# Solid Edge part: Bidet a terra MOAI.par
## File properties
Title: Bidet a terra MOAI
Author: DESYS
Template: Iso Part.par
Last saved by: PIM
Revision: 18
Application: Solid Edge
Tipo di contenuto documento: 0
Accuracy: 0,990
Document Number: 8607
Revision: 0
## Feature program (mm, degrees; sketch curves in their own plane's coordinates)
lofted protrusion "unnamed LoftedProtrusion 1"
lofted protrusion "unnamed LoftedProtrusion 2"
lofted protrusion "unnamed LoftedProtrusion 3"
lofted cutout "unnamed LoftedCutout 1"
thinwall "Spessoramento_2"  Thickness = 19 mm
thinwall "unnamed Thinwall 1"
thinwall "Spessoramento_4"  Thickness = 19 mm
sketch for "ProtrusioneEstrusa_1" plane through (-0.2644, 26.5251, -190) normal (0, 0, -1) x-axis (0, 1, 0)
  arc centre (3.4749, 0.2644) radius 35 from (-5.8954, -33.458) to (38.4749, 0.2644) ccw
  arc centre (3.4749, 0.2644) radius 35 from (38.4749, 0.2644) to (-22.0299, 24.2333) ccw
  arc centre (3.4749, 0.2644) radius 35 from (-22.0299, 24.2333) to (-31.5251, 0.2644) ccw
  arc centre (3.4749, 0.2644) radius 35 from (-31.5251, 0.2644) to (-21.0549, -24.7014) ccw
  arc centre (3.4749, 0.2644) radius 35 from (-21.0549, -24.7014) to (-5.8954, -33.458) ccw
extrude "ProtrusioneEstrusa_1" add through along -normal  Profile_Plane1_Distance = 15 mm
sketch for "unnamed Cutout 1" plane through (0.0007, 30, -150) normal (0, 0, 1) x-axis (-1, 0, 0)
  circle centre (0.0007, 0) radius 25
extrude "unnamed Cutout 1" cut through along -normal
sketch for "Foro_1" plane through (0, 54.9995, 0) normal (0, 0, 1) x-axis (-1, 0, 0)
  hole centre (0.0739, 199.9995) bore radius 17.5
hole "Foro_1" diameter 35 through
sketch for "ProtrusioneEstrusa_2"
  line (-125.0641, -18.0787) -> (-63.2077, -192.1962)
  line (-63.2077, -192.1962) -> (0.0001, -198.7066)
  line (0.0001, -159.2025) -> (0.0001, -198.7066)
  line (-44.6271, -121.0257) -> (0.0001, -159.2025)
  line (-90.7805, -18.0787) -> (-44.6271, -121.0257)
  line (-125.0641, -18.0787) -> (-90.7805, -18.0787)
extrude "ProtrusioneEstrusa_2" add finite 40 symmetric
fillet "Rotondo_1" radius 10
fillet "Rotondo_4" radius 5
sketch for "unnamed Cutout 2" plane through (0, -220, -205) normal (0, -1, 0) x-axis (1, 0, 0)
  line (88.2361, 175) -> (-88.2392, 175)
  arc centre (-88.2392, 150) radius 25 from (-88.2392, 175) to (-113.2363, 150.3801) ccw
  arc centre (1686.5556, 123.01) radius 1800 from (-113.2363, 150.3801) to (-92.0257, -153.8449) ccw
  arc centre (-67.3232, -149.9997) radius 25 from (-92.0257, -153.8449) to (-67.3232, -174.9997) ccw
  line (67.3229, -175) -> (-67.3232, -174.9997)
  arc centre (67.3229, -150) radius 25 from (67.3229, -175) to (92.0255, -153.8449) ccw
  arc centre (-1686.6002, 122.9957) radius 1800.0418 from (113.2332, 150.3803) to (92.0255, -153.8449) cw
  arc centre (88.2361, 150) radius 25 from (113.2332, 150.3803) to (88.2361, 175) ccw
  dimension (radial) = 0.0001
extrude "unnamed Cutout 2" cut through along -normal
fillet "Rotondo_9" radius 20
fillet "Rotondo_10" radius 5
fillet "Rotondo_12" radius 10
fillet "Rotondo_13" radius 5
sketch for "ProtrusioneEstrusa_3" plane through (0, 0, 0) normal (1, 0, 0) x-axis (0, 1, 0)
  line (-119.4631, -19) -> (-66.4893, -145.719)
  arc centre (-26.7858, -129.1213) radius 43.0331 from (-66.4893, -145.719) to (-37.7196, -170.7422) ccw
  line (-37.7196, -170.7422) -> (-5, -179.3377)
extrude "ProtrusioneEstrusa_3" add finite 40 symmetric
fillet "Rotondo_14" radius 5
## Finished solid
Body 1: solid body, 63 faces, 178 edges, 118 vertices.
  Faces by surface: cylinder 22, blend 12, plane 12, torus 10, offset 4, spline 3
  Edges by curve: intersection 65, circle 61, line 39, ellipse 8, curve on surface 4, spline 1
Bounding box of the edges (mm; curved faces can reach further): 383.076 x 550.236 x 410.000, from (-191.5381, -220, -410) to (191.5378, 330.2365, 0).
Cylindrical faces by radius (mm): R5 x11, R10 x1, R17.5 x1, R25 x5, R35 x1, R43.0331 x1, R1800 x1, R1800.0418 x1
Toroidal faces (ring radius, tube radius in mm): R22.5 r5 x1, R30 r5 x5, R38.0331 r5 x2, R1805 r5 x1, R1805.0418 r5 x1
Planar faces by outward normal: +x 1, +y 1, +z 2, -x 1, -y 1, -z 4, oblique 2
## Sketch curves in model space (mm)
arc centre (-523.5682, -220, -166.8251) radius 660 from (115, -220, 0) through (135.2082, -220, -206.9944) to (90, -220, -410)
arc centre (523.5682, -220, -166.8251) radius 660 from (-115, -220, 0) through (-135.2082, -220, -206.9944) to (-90, -220, -410)
arc centre (-47.8777, 30, 36.2494) radius 200 from (25, 30, -150) through (106.3667, 30, -91.0638) to (148.8098, 30, 0)
arc centre (48.0699, 30, 36.1741) radius 200 from (-25, 30, -150) through (-106.2646, 30, -91.0299) to (-148.6315, 30, 0)
arc centre (0, 119.5124, 13.9723) radius 200 from (0, 5, -150) through (0, -54.4926, -84.6293) to (0, -79.999, 0)
arc centre (0, 29.5721, 148.9204) radius 300 from (0, 290, 0) through (0, 190.9827, -103.9562) to (0, 55, -150)
circle centre (0, 30, -150) radius 25
arc centre (-49.1984, 40.6323, 0) radius 100 from (-119.9304, -30.0571, 0) through (-142.7572, 5.3229, 0) to (-148.9978, 46.9626, 0)
ellipse centre (0, 15.2559, 0) radii 274.7441, 150 from (149.0825, 45.5968, 0) through (-8.5444, 289.5539, 0) to (-148.9978, 46.9626, 0)
arc centre (49.266, 39.5415, 0) radius 100 from (118.4148, -32.6973, 0) through (142.3778, 3.0697, 0) to (149.0825, 45.5968, 0)
arc centre (0.5911, 90.3917, 0) radius 170.3917 from (118.4148, -32.6973, 0) through (-1.2963, -79.9895, 0) to (-119.9304, -30.0571, 0)
arc centre (619.961, 0, -156.6009) radius 824.961 from (-190, 0, 0) through (-203.4851, 0, -206.5734) to (-165.1183, 0, -410)
arc centre (-619.961, 0, -156.6009) radius 824.961 from (190, 0, 0) through (203.4851, 0, -206.5734) to (165.1183, 0, -410)
arc centre (0, -869.5225, -33.8504) radius 1200 from (0, 330, 0) through (0, 317.8308, -207.6094) to (0, 270, -410)
arc centre (-363.7284, 60.9197, -410) radius 533.6528 from (159.9051, -42.004, -410) through (132.9906, -134.1588, -410) to (90, -220, -410)
arc centre (-134.4624, 15.8559, -410) radius 300 from (163.3957, 51.6411, -410) through (165.3294, 4.6814, -410) to (159.9051, -42.004, -410)
ellipse centre (0, 0, -410) radii 270, 166.4689 from (163.3957, 51.6411, -410) through (-9.9702, 269.5153, -410) to (-163.3957, 51.6411, -410)
arc centre (134.4624, 15.8559, -410) radius 300 from (-163.3957, 51.6411, -410) through (-165.3294, 4.6814, -410) to (-159.9051, -42.004, -410)
arc centre (363.7284, 60.9197, -410) radius 533.6528 from (-159.9051, -42.004, -410) through (-132.9906, -134.1588, -410) to (-90, -220, -410)
line (-90, -220, -410) -> (90, -220, -410)
arc centre (-200.6442, 38.2369, 0) radius 407.8205 from (138.9981, -187.5077, 0) through (127.4016, -204.0512, 0) to (115, -220, 0)
arc centre (-110.8488, -21.446, 0) radius 300 from (138.9981, -187.5077, 0) through (172.6583, -119.5466, 0) to (188.2, -45.3161, 0)
ellipse centre (0, 0, 0) radii 330, 190 from (-188.2, -45.3161, 0) through (0, 330, 0) to (188.2, -45.3161, 0)
arc centre (110.8488, -21.446, 0) radius 300 from (-188.2, -45.3161, 0) through (-172.6583, -119.5466, 0) to (-138.9981, -187.5077, 0)
arc centre (200.6442, 38.2369, 0) radius 407.8205 from (-138.9981, -187.5077, 0) through (-127.4016, -204.0512, 0) to (-115, -220, 0)
line (-115, -220, 0) -> (115, -220, 0)
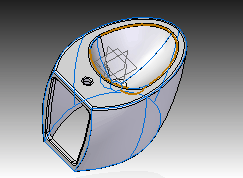
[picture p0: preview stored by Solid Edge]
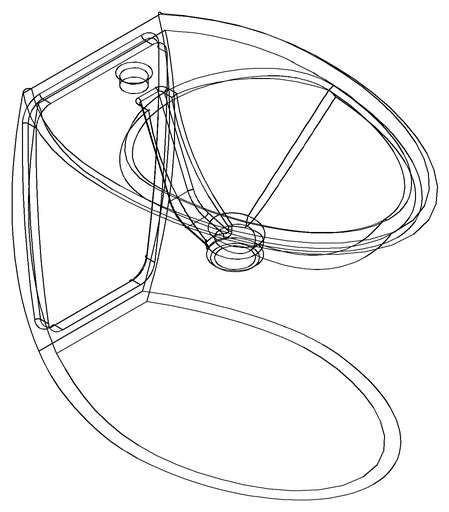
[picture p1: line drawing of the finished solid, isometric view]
